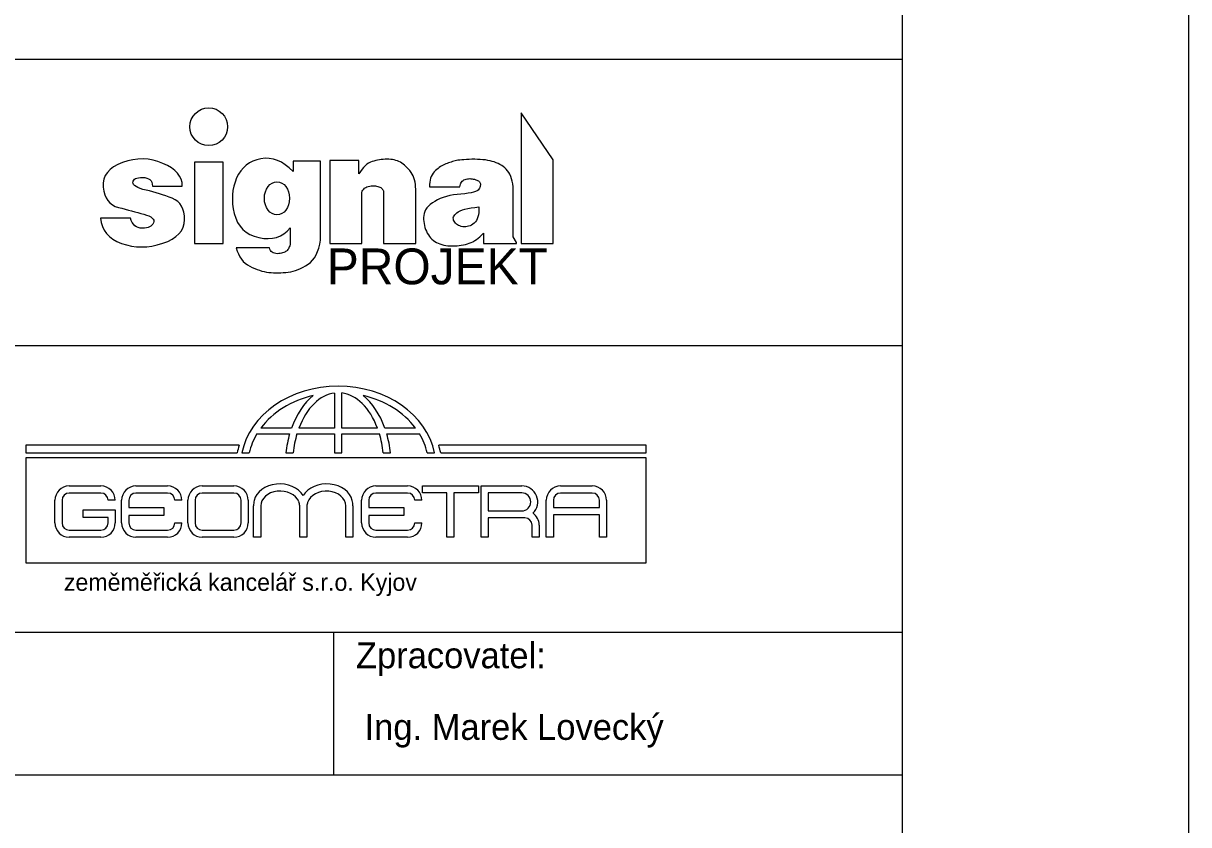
# Model space of a CAD drawing. Extents: x 3181 to 4881, y -3016 to -2572.
# Drawn here: x 4054.2 to 4135.6, y -2917.2 to -2861.3 of the extents above; entities that cross this region are included whole.
import ezdxf

# ---------------------------------------------------------------- set-up
doc = ezdxf.new("R2010")
doc.units = 0
for name, color, linetype in [('Default', 7, 'Continuous'), ('Vrstva 1', 7, 'Continuous'), ('Vrstva 11', 7, 'Continuous'), ('Vrstva 17', 7, 'Continuous'), ('Vrstva 6', 7, 'Continuous')]:
    doc.layers.add(name, color=color, linetype=linetype)

msp = doc.modelspace()

# ---------------------------------------------------------------- linework, layer by layer
at = {"layer": 'Default'}
msp.add_lwpolyline([(3925.563, -3015.765), (4135.563, -3015.765), (4135.563, -2718.765), (3925.563, -2718.765)], close=True, dxfattribs=at)
at = {"layer": 'Vrstva 1'}
msp.add_lwpolyline([(3945.563, -2738.765), (4115.563, -2738.765), (4115.563, -2998.765), (3945.563, -2998.765)], close=True, dxfattribs=at)
at = {"layer": 'Vrstva 11'}
for points in [[(4091.228, -2876.644), (4091.228, -2870.804), (4088.988, -2867.524), (4088.988, -2876.644), (4091.228, -2876.644)], [(4062.499, -2876.879), (4062.861, -2876.862), (4063.228, -2876.814), (4063.599, -2876.735), (4063.975, -2876.625), (4064.329, -2876.489), (4064.637, -2876.333), (4064.898, -2876.157), (4065.112, -2875.961), (4065.28, -2875.745), (4065.4, -2875.509), (4065.474, -2875.253), (4065.5, -2874.977), (4065.49, -2874.704), (4065.451, -2874.455), (4065.385, -2874.231), (4065.291, -2874.031), (4065.17, -2873.856), (4065.021, -2873.706), (4064.844, -2873.581), (4064.639, -2873.48), (4064.42, -2873.394), (4064.198, -2873.312), (4063.973, -2873.235), (4063.747, -2873.162), (4063.518, -2873.094), (4063.287, -2873.029), (4063.054, -2872.97), (4062.818, -2872.914), (4062.596, -2872.859), (4062.405, -2872.8), (4062.244, -2872.737), (4062.114, -2872.67), (4062.014, -2872.599), (4061.945, -2872.524), (4061.906, -2872.445), (4061.897, -2872.362), (4061.914, -2872.282), (4061.95, -2872.213), (4062.006, -2872.155), (4062.082, -2872.108), (4062.178, -2872.072), (4062.294, -2872.046), (4062.429, -2872.032), (4062.585, -2872.028), (4062.74, -2872.039), (4062.875, -2872.068), (4062.99, -2872.115), (4063.085, -2872.181), (4063.16, -2872.265), (4063.214, -2872.367), (4063.249, -2872.487), (4063.263, -2872.626), (4065.342, -2872.626), (4065.323, -2872.384), (4065.261, -2872.155), (4065.156, -2871.937), (4065.008, -2871.733), (4064.817, -2871.542), (4064.583, -2871.363), (4064.307, -2871.197), (4063.987, -2871.043), (4063.645, -2870.914), (4063.3, -2870.819), (4062.952, -2870.76), (4062.602, -2870.735), (4062.249, -2870.745), (4061.894, -2870.79), (4061.535, -2870.869), (4061.174, -2870.984), (4060.836, -2871.126), (4060.547, -2871.289), (4060.306, -2871.472), (4060.114, -2871.676), (4059.971, -2871.901), (4059.876, -2872.145), (4059.83, -2872.411), (4059.832, -2872.697), (4059.872, -2872.978), (4059.938, -2873.23), (4060.03, -2873.453), (4060.148, -2873.645), (4060.293, -2873.809), (4060.464, -2873.943), (4060.661, -2874.047), (4060.885, -2874.122), (4061.12, -2874.182), (4061.351, -2874.241), (4061.578, -2874.3), (4061.802, -2874.359), (4062.023, -2874.418), (4062.239, -2874.476), (4062.452, -2874.534), (4062.662, -2874.592), (4062.854, -2874.652), (4063.016, -2874.716), (4063.146, -2874.785), (4063.246, -2874.859), (4063.314, -2874.937), (4063.352, -2875.019), (4063.359, -2875.106), (4063.335, -2875.197), (4063.289, -2875.285), (4063.228, -2875.362), (4063.152, -2875.426), (4063.062, -2875.479), (4062.958, -2875.521), (4062.84, -2875.551), (4062.707, -2875.569), (4062.559, -2875.576), (4062.411, -2875.566), (4062.275, -2875.532), (4062.152, -2875.477), (4062.04, -2875.398), (4061.942, -2875.297), (4061.855, -2875.173), (4061.781, -2875.027), (4061.72, -2874.858), (4059.639, -2874.858), (4059.683, -2875.165), (4059.767, -2875.447), (4059.89, -2875.705), (4060.052, -2875.939), (4060.254, -2876.148), (4060.496, -2876.333), (4060.778, -2876.494), (4061.099, -2876.631), (4061.442, -2876.74), (4061.79, -2876.817), (4062.142, -2876.864), (4062.499, -2876.879)], [(4068.188, -2876.644), (4068.188, -2870.964), (4066.188, -2870.964), (4066.188, -2876.644), (4068.188, -2876.644)], [(4072.047, -2878.686), (4072.216, -2878.682), (4072.386, -2878.674), (4072.558, -2878.66), (4072.731, -2878.642), (4072.905, -2878.615), (4073.079, -2878.576), (4073.253, -2878.525), (4073.426, -2878.462), (4073.6, -2878.386), (4073.772, -2878.298), (4073.945, -2878.199), (4074.117, -2878.087), (4074.282, -2877.957), (4074.43, -2877.804), (4074.563, -2877.629), (4074.679, -2877.43), (4074.78, -2877.208), (4074.865, -2876.963), (4074.934, -2876.695), (4074.988, -2876.404), (4074.988, -2870.884), (4073.068, -2870.884), (4073.068, -2871.604), (4072.802, -2871.349), (4072.531, -2871.136), (4072.257, -2870.964), (4071.978, -2870.833), (4071.695, -2870.743), (4071.407, -2870.694), (4071.116, -2870.687), (4070.82, -2870.72), (4070.533, -2870.788), (4070.267, -2870.885), (4070.024, -2871.011), (4069.802, -2871.164), (4069.602, -2871.347), (4069.423, -2871.558), (4069.267, -2871.797), (4069.132, -2872.065), (4069.022, -2872.351), (4068.937, -2872.644), (4068.878, -2872.944), (4068.845, -2873.251), (4068.838, -2873.566), (4068.857, -2873.888), (4068.901, -2874.216), (4068.972, -2874.553), (4069.072, -2874.876), (4069.205, -2875.167), (4069.37, -2875.425), (4069.568, -2875.65), (4069.799, -2875.843), (4070.062, -2876.003), (4070.358, -2876.13), (4070.687, -2876.225), (4071.023, -2876.283), (4071.342, -2876.3), (4071.643, -2876.277), (4071.926, -2876.213), (4072.191, -2876.108), (4072.438, -2875.963), (4072.668, -2875.776), (4072.88, -2875.55), (4072.88, -2876.626), (4072.861, -2876.714), (4072.838, -2876.796), (4072.81, -2876.871), (4072.778, -2876.942), (4072.742, -2877.006), (4072.701, -2877.065), (4072.655, -2877.118), (4072.605, -2877.165), (4072.55, -2877.207), (4072.487, -2877.243), (4072.417, -2877.274), (4072.34, -2877.3), (4072.256, -2877.32), (4072.165, -2877.335), (4072.067, -2877.344), (4071.962, -2877.348), (4071.858, -2877.343), (4071.765, -2877.324), (4071.682, -2877.292), (4071.609, -2877.247), (4071.546, -2877.189), (4071.493, -2877.117), (4071.451, -2877.032), (4071.418, -2876.934), (4069.111, -2876.934), (4069.18, -2877.162), (4069.264, -2877.371), (4069.361, -2877.561), (4069.472, -2877.732), (4069.596, -2877.885), (4069.735, -2878.019), (4069.887, -2878.134), (4070.053, -2878.23), (4070.225, -2878.313), (4070.396, -2878.387), (4070.565, -2878.453), (4070.733, -2878.51), (4070.899, -2878.558), (4071.064, -2878.598), (4071.227, -2878.629), (4071.389, -2878.652), (4071.551, -2878.668), (4071.715, -2878.679), (4071.88, -2878.685), (4072.047, -2878.686)], [(4081.628, -2876.644), (4081.628, -2872.844), (4081.624, -2872.674), (4081.61, -2872.511), (4081.586, -2872.354), (4081.55, -2872.204), (4081.504, -2872.06), (4081.447, -2871.924), (4081.379, -2871.793), (4081.301, -2871.67), (4081.216, -2871.553), (4081.129, -2871.445), (4081.04, -2871.345), (4080.949, -2871.254), (4080.856, -2871.17), (4080.761, -2871.095), (4080.664, -2871.028), (4080.565, -2870.969), (4080.462, -2870.918), (4080.356, -2870.873), (4080.245, -2870.836), (4080.13, -2870.806), (4080.011, -2870.782), (4079.887, -2870.765), (4079.759, -2870.756), (4079.627, -2870.753), (4079.493, -2870.756), (4079.361, -2870.764), (4079.229, -2870.777), (4079.099, -2870.795), (4078.97, -2870.818), (4078.842, -2870.846), (4078.716, -2870.879), (4078.59, -2870.917), (4078.467, -2870.965), (4078.345, -2871.03), (4078.226, -2871.111), (4078.11, -2871.209), (4077.996, -2871.323), (4077.884, -2871.453), (4077.775, -2871.6), (4077.668, -2871.764), (4077.668, -2870.844), (4075.628, -2870.844), (4075.628, -2876.644), (4077.868, -2876.644), (4077.868, -2873.084), (4077.902, -2872.993), (4077.946, -2872.912), (4078.001, -2872.841), (4078.065, -2872.78), (4078.139, -2872.729), (4078.223, -2872.688), (4078.317, -2872.657), (4078.421, -2872.636), (4078.527, -2872.623), (4078.628, -2872.616), (4078.723, -2872.615), (4078.814, -2872.62), (4078.899, -2872.632), (4078.978, -2872.649), (4079.053, -2872.673), (4079.122, -2872.703), (4079.184, -2872.737), (4079.238, -2872.776), (4079.284, -2872.818), (4079.321, -2872.864), (4079.35, -2872.913), (4079.371, -2872.966), (4079.383, -2873.023), (4079.388, -2873.084), (4079.388, -2876.644), (4081.628, -2876.644)], [(4084.19, -2876.808), (4084.352, -2876.805), (4084.51, -2876.796), (4084.663, -2876.782), (4084.812, -2876.762), (4084.956, -2876.736), (4085.097, -2876.705), (4085.233, -2876.667), (4085.364, -2876.624), (4085.493, -2876.573), (4085.62, -2876.511), (4085.746, -2876.44), (4085.869, -2876.357), (4085.991, -2876.264), (4086.112, -2876.161), (4086.23, -2876.048), (4086.348, -2875.924), (4086.348, -2876.644), (4088.668, -2876.644), (4088.668, -2876.564), (4088.428, -2876.164), (4088.428, -2872.684), (4088.401, -2872.479), (4088.365, -2872.289), (4088.32, -2872.113), (4088.265, -2871.952), (4088.201, -2871.805), (4088.127, -2871.673), (4088.043, -2871.555), (4087.95, -2871.452), (4087.849, -2871.359), (4087.742, -2871.273), (4087.628, -2871.195), (4087.508, -2871.123), (4087.382, -2871.058), (4087.25, -2871), (4087.111, -2870.948), (4086.966, -2870.904), (4086.814, -2870.866), (4086.655, -2870.834), (4086.489, -2870.808), (4086.315, -2870.787), (4086.135, -2870.772), (4085.947, -2870.763), (4085.751, -2870.759), (4085.549, -2870.761), (4085.35, -2870.767), (4085.166, -2870.775), (4084.997, -2870.786), (4084.843, -2870.799), (4084.703, -2870.814), (4084.578, -2870.831), (4084.467, -2870.85), (4084.372, -2870.872), (4084.283, -2870.896), (4084.194, -2870.921), (4084.104, -2870.949), (4084.013, -2870.978), (4083.921, -2871.01), (4083.829, -2871.043), (4083.737, -2871.079), (4083.643, -2871.116), (4083.55, -2871.158), (4083.458, -2871.206), (4083.366, -2871.262), (4083.276, -2871.324), (4083.187, -2871.393), (4083.099, -2871.469), (4083.012, -2871.551), (4082.926, -2871.641), (4082.845, -2871.738), (4082.776, -2871.845), (4082.718, -2871.962), (4082.67, -2872.087), (4082.633, -2872.222), (4082.607, -2872.367), (4082.592, -2872.521), (4082.588, -2872.684), (4084.708, -2872.684), (4084.723, -2872.587), (4084.747, -2872.5), (4084.78, -2872.422), (4084.821, -2872.353), (4084.872, -2872.294), (4084.93, -2872.243), (4084.998, -2872.202), (4085.073, -2872.169), (4085.154, -2872.145), (4085.235, -2872.127), (4085.317, -2872.116), (4085.399, -2872.111), (4085.481, -2872.113), (4085.565, -2872.121), (4085.648, -2872.136), (4085.732, -2872.157), (4085.813, -2872.183), (4085.884, -2872.211), (4085.947, -2872.24), (4086, -2872.272), (4086.045, -2872.307), (4086.082, -2872.343), (4086.109, -2872.381), (4086.128, -2872.422), (4086.14, -2872.465), (4086.145, -2872.511), (4086.144, -2872.559), (4086.136, -2872.611), (4086.122, -2872.665), (4086.103, -2872.722), (4086.076, -2872.782), (4086.044, -2872.844), (4085.993, -2872.905), (4085.912, -2872.961), (4085.801, -2873.012), (4085.659, -2873.057), (4085.487, -2873.097), (4085.285, -2873.132), (4085.052, -2873.162), (4084.789, -2873.186), (4084.517, -2873.212), (4084.258, -2873.25), (4084.01, -2873.298), (4083.775, -2873.356), (4083.553, -2873.425), (4083.342, -2873.505), (4083.144, -2873.595), (4082.958, -2873.695), (4082.789, -2873.804), (4082.641, -2873.916), (4082.513, -2874.033), (4082.407, -2874.155), (4082.321, -2874.281), (4082.256, -2874.412), (4082.212, -2874.547), (4082.189, -2874.687), (4082.181, -2874.828), (4082.182, -2874.968), (4082.192, -2875.107), (4082.211, -2875.245), (4082.239, -2875.382), (4082.276, -2875.517), (4082.322, -2875.652), (4082.377, -2875.785), (4082.44, -2875.913), (4082.51, -2876.032), (4082.587, -2876.143), (4082.671, -2876.244), (4082.761, -2876.337), (4082.859, -2876.421), (4082.964, -2876.495), (4083.075, -2876.562), (4083.193, -2876.619), (4083.317, -2876.669), (4083.447, -2876.712), (4083.584, -2876.746), (4083.726, -2876.773), (4083.875, -2876.792), (4084.03, -2876.804), (4084.19, -2876.808)], [(4084.906, -2875.463), (4084.803, -2875.443), (4084.708, -2875.415), (4084.622, -2875.379), (4084.543, -2875.335), (4084.472, -2875.284), (4084.409, -2875.225), (4084.354, -2875.158), (4084.307, -2875.083), (4084.273, -2875.006), (4084.255, -2874.929), (4084.254, -2874.853), (4084.27, -2874.778), (4084.302, -2874.703), (4084.351, -2874.63), (4084.417, -2874.558), (4084.5, -2874.486), (4084.603, -2874.418), (4084.732, -2874.355), (4084.886, -2874.297), (4085.065, -2874.245), (4085.269, -2874.198), (4085.498, -2874.156), (4085.753, -2874.119), (4086.032, -2874.088), (4086.037, -2874.287), (4086.028, -2874.469), (4086.006, -2874.635), (4085.972, -2874.784), (4085.924, -2874.918), (4085.864, -2875.035), (4085.79, -2875.137), (4085.704, -2875.222), (4085.611, -2875.293), (4085.515, -2875.353), (4085.418, -2875.4), (4085.319, -2875.436), (4085.219, -2875.461), (4085.116, -2875.473), (4085.012, -2875.474), (4084.906, -2875.463)]]:
    msp.add_lwpolyline(points, dxfattribs=at)
msp.add_circle((4067.188, -2868.484), 1.32, dxfattribs=at)
msp.add_ellipse((4071.948, -2873.484), major_axis=(0, 1.16), ratio=0.758621, dxfattribs=at)
at = {"layer": 'Vrstva 17'}
for p, q in [((4075.958, -2887.077), (4075.958, -2889.523)), ((4076.465, -2889.523), (4076.465, -2887.075)), ((4072.965, -2889.523), (4070.82, -2889.523)), ((4075.958, -2889.523), (4073.482, -2889.523)), ((4078.96, -2889.523), (4076.465, -2889.523)), ((4081.622, -2889.523), (4079.477, -2889.523)), ((4070.545, -2889.935), (4072.832, -2889.935)), ((4073.342, -2889.935), (4075.958, -2889.935)), ((4075.958, -2889.935), (4075.958, -2891.255)), ((4076.465, -2891.255), (4076.465, -2889.935)), ((4076.465, -2889.935), (4079.099, -2889.935)), ((4079.609, -2889.935), (4081.897, -2889.935)), ((4069.314, -2890.724), (4054.433, -2890.724)), ((4054.433, -2890.724), (4054.433, -2891.255)), ((4054.433, -2891.255), (4069.176, -2891.255)), ((4069.502, -2891.255), (4070.019, -2891.255)), ((4072.575, -2891.255), (4073.075, -2891.255)), ((4075.958, -2891.255), (4076.465, -2891.255)), ((4079.366, -2891.255), (4079.866, -2891.255)), ((4082.423, -2891.255), (4082.94, -2891.255)), ((4097.712, -2890.724), (4083.233, -2890.724)), ((4083.371, -2891.255), (4097.712, -2891.255)), ((4097.712, -2891.255), (4097.712, -2890.724)), ((4097.71, -2891.599), (4054.427, -2891.599)), ((4054.427, -2891.599), (4054.427, -2898.937)), ((4097.71, -2898.937), (4097.71, -2891.599)), ((4057.452, -2893.565), (4059.663, -2893.565)), ((4062.108, -2893.565), (4064.319, -2893.565)), ((4066.732, -2893.565), (4068.943, -2893.565)), ((4078.851, -2893.565), (4081.061, -2893.565)), ((4086.188, -2893.565), (4089.032, -2893.565)), ((4091.736, -2893.565), (4093.947, -2893.565)), ((4056.454, -2896.149), (4056.454, -2894.563)), ((4056.953, -2894.563), (4056.953, -2896.149)), ((4059.663, -2894.064), (4057.452, -2894.064)), ((4060.66, -2894.563), (4060.162, -2894.563)), ((4061.11, -2896.149), (4061.11, -2894.563)), ((4061.609, -2894.563), (4061.609, -2895.074)), ((4064.319, -2894.064), (4062.108, -2894.064)), ((4065.317, -2894.563), (4064.818, -2894.563)), ((4065.734, -2896.149), (4065.734, -2894.563)), ((4066.233, -2894.563), (4066.233, -2896.149)), ((4068.943, -2894.064), (4066.732, -2894.064)), ((4069.442, -2896.149), (4069.442, -2894.563)), ((4069.941, -2894.563), (4069.941, -2896.149)), ((4077.853, -2896.149), (4077.853, -2894.563)), ((4078.352, -2894.563), (4078.352, -2895.074)), ((4081.061, -2894.064), (4078.851, -2894.064)), ((4082.059, -2894.563), (4081.56, -2894.563)), ((4083.794, -2897.147), (4083.794, -2894.052)), ((4084.297, -2894.052), (4084.297, -2897.147)), ((4089.032, -2894.054), (4086.692, -2894.054)), ((4086.692, -2894.054), (4086.692, -2895.304)), ((4090.738, -2897.147), (4090.738, -2894.563)), ((4091.237, -2894.563), (4091.237, -2895.072)), ((4093.947, -2894.064), (4091.736, -2894.064)), ((4094.446, -2895.072), (4094.446, -2894.563)), ((4094.945, -2894.563), (4094.945, -2897.147)), ((4058.427, -2895.771), (4058.427, -2895.227)), ((4058.427, -2895.227), (4060.66, -2895.227)), ((4060.66, -2895.227), (4060.66, -2896.149)), ((4061.609, -2895.074), (4064.052, -2895.074)), ((4064.052, -2895.074), (4064.052, -2895.618)), ((4070.313, -2897.147), (4070.313, -2894.962)), ((4070.814, -2894.962), (4070.814, -2897.147)), ((4073.533, -2897.147), (4073.533, -2894.962)), ((4074.033, -2894.962), (4074.033, -2897.147)), ((4076.752, -2897.147), (4076.752, -2894.962)), ((4077.253, -2894.962), (4077.253, -2897.147)), ((4078.352, -2895.074), (4080.795, -2895.074)), ((4080.795, -2895.074), (4080.795, -2895.618)), ((4086.692, -2895.304), (4089.032, -2895.304)), ((4091.237, -2895.072), (4094.446, -2895.072)), ((4060.162, -2895.771), (4058.427, -2895.771)), ((4060.162, -2896.149), (4060.162, -2895.771)), ((4064.052, -2895.618), (4061.609, -2895.618)), ((4061.609, -2895.618), (4061.609, -2896.149)), ((4064.818, -2896.149), (4065.317, -2896.149)), ((4080.795, -2895.618), (4078.352, -2895.618)), ((4078.352, -2895.618), (4078.352, -2896.149)), ((4081.56, -2896.149), (4082.059, -2896.149)), ((4089.032, -2895.793), (4086.692, -2895.793)), ((4089.247, -2895.797), (4089.032, -2895.793)), ((4089.746, -2897.147), (4089.746, -2896.296)), ((4090.244, -2896.296), (4090.244, -2897.147)), ((4094.446, -2895.575), (4091.237, -2895.575)), ((4091.237, -2895.575), (4091.237, -2897.147)), ((4094.446, -2897.147), (4094.446, -2895.575)), ((4057.452, -2896.648), (4059.663, -2896.648)), ((4059.663, -2897.147), (4057.452, -2897.147)), ((4062.108, -2896.648), (4064.319, -2896.648)), ((4064.319, -2897.147), (4062.108, -2897.147)), ((4066.732, -2896.648), (4068.943, -2896.648)), ((4068.943, -2897.147), (4066.732, -2897.147)), ((4070.814, -2897.147), (4070.313, -2897.147)), ((4074.033, -2897.147), (4073.533, -2897.147)), ((4077.253, -2897.147), (4076.752, -2897.147)), ((4078.851, -2896.648), (4081.061, -2896.648)), ((4081.061, -2897.147), (4078.851, -2897.147)), ((4084.297, -2897.147), (4083.794, -2897.147)), ((4090.244, -2897.147), (4089.746, -2897.147)), ((4091.237, -2897.147), (4090.738, -2897.147)), ((4094.945, -2897.147), (4094.446, -2897.147)), ((4054.427, -2898.937), (4097.71, -2898.937))]:
    msp.add_line(p, q, dxfattribs=at)
for points in [[(4083.794, -2894.052), (4082.096, -2894.052), (4082.096, -2893.565), (4086.009, -2893.565)], [(4086.009, -2893.565), (4086.009, -2894.052), (4084.297, -2894.052)], [(4086.692, -2895.793), (4086.692, -2897.147), (4086.188, -2897.147), (4086.188, -2893.565)]]:
    msp.add_lwpolyline(points, dxfattribs=at)
for centre, radius, start, end in [((4057.452, -2894.563), 0.998, 90, 180), ((4059.663, -2894.563), 0.998, 360, 90), ((4062.108, -2894.563), 0.998, 90, 180), ((4064.319, -2894.563), 0.998, 360, 90), ((4066.732, -2894.563), 0.998, 90, 180), ((4068.943, -2894.563), 0.998, 360, 90), ((4078.851, -2894.563), 0.998, 90, 180), ((4081.061, -2894.563), 0.998, 360, 90), ((4089.032, -2894.679), 1.114, 314.45734, 90), ((4091.736, -2894.563), 0.998, 90, 180), ((4093.947, -2894.563), 0.998, 360, 90), ((4057.452, -2894.563), 0.499, 90, 180), ((4059.663, -2894.563), 0.499, 0, 90), ((4062.108, -2894.563), 0.499, 90, 180), ((4064.319, -2894.563), 0.499, 0, 90), ((4066.732, -2894.563), 0.499, 90, 180), ((4068.943, -2894.563), 0.499, 0, 90), ((4072.25, -2895.012), 1.938, 166.96576, 178.52091), ((4072.579, -2895.027), 0.957, 3.86486, 22.41569), ((4075.266, -2895.084), 1.238, 162.61388, 174.3506), ((4075.315, -2895.012), 1.938, 1.47909, 13.03424), ((4078.851, -2894.563), 0.499, 90, 180), ((4081.061, -2894.563), 0.499, 0, 90), ((4089.032, -2894.679), 0.625, 270, 90), ((4091.736, -2894.563), 0.499, 90, 180), ((4093.947, -2894.563), 0.499, 0, 90), ((4089.247, -2896.296), 0.998, 360, 55.44734), ((4057.452, -2896.149), 0.998, 180, 270), ((4057.452, -2896.149), 0.499, 180, 270), ((4059.663, -2896.149), 0.998, 270, 0), ((4059.663, -2896.149), 0.499, 270, 0), ((4062.108, -2896.149), 0.998, 180, 270), ((4062.108, -2896.149), 0.499, 180, 270), ((4064.319, -2896.149), 0.998, 270, 0), ((4064.319, -2896.149), 0.499, 270, 0), ((4066.732, -2896.149), 0.998, 180, 270), ((4066.732, -2896.149), 0.499, 180, 270), ((4068.943, -2896.149), 0.998, 270, 0), ((4068.943, -2896.149), 0.499, 270, 0), ((4078.851, -2896.149), 0.998, 180, 270), ((4078.851, -2896.149), 0.499, 180, 270), ((4081.061, -2896.149), 0.998, 270, 0), ((4081.061, -2896.149), 0.499, 270, 0), ((4089.247, -2896.296), 0.499, 0, 90)]:
    msp.add_arc(centre, radius, start, end, dxfattribs=at)
for centre, major_axis, ratio, start_param, end_param in [((4076.221, -2892.127), (-6.804, 0), 0.811768, 3.300239, 6.124539), ((4076.221, -2892.127), (-6.296, 0), 0.804826, 4.992897, 5.743383), ((4076.221, -2892.127), (0, 5.524), 0.668443, 0.491666, 1.079789), ((4076.221, -2892.127), (0, 5.067), 0.630136, 0.08224, 1.030995), ((4076.221, -2892.127), (0, 5.067), 0.630136, 5.252191, 6.206521), ((4076.221, -2892.127), (0, 5.524), 0.668443, 5.203397, 5.79152), ((4076.221, -2892.127), (-6.296, 0), 0.804826, 3.681394, 4.431881), ((4076.221, -2892.127), (-6.296, 0), 0.804826, 5.835664, 6.110118), ((4076.221, -2892.127), (0, 5.524), 0.668443, 1.16256, 1.41215), ((4076.221, -2892.127), (0, 5.067), 0.630136, 1.123275, 1.397729), ((4076.221, -2892.127), (0, 5.067), 0.630136, 4.885456, 5.159911), ((4076.221, -2892.127), (0, 5.524), 0.668443, 4.871035, 5.120625), ((4076.221, -2892.127), (-6.296, 0), 0.804826, 3.31466, 3.589114), ((4075.895, -2892.127), (-6.804, 0), 0.811768, 6.026233, 6.124539), ((4076.653, -2892.127), (-6.804, 0), 0.811768, 3.300239, 3.398545), ((4072.142, -2894.807), (1.805, 0), 0.766187, 0.429647, 2.97338), ((4072.167, -2894.962), (1.354, 0), 0.766187, 0.29376, 3.141593), ((4075.424, -2894.807), (-1.805, 0), 0.766187, 3.309805, 5.853538), ((4075.398, -2894.962), (-1.354, 0), 0.766187, 3.141593, 6.041607)]:
    msp.add_ellipse(centre, major_axis=major_axis, ratio=ratio, start_param=start_param, end_param=end_param, dxfattribs=at)
at = {"layer": 'Vrstva 6'}
for p, q in [((3945.563, -2883.765), (4115.563, -2883.765)), ((3945.563, -2903.765), (4115.563, -2903.765)), ((4075.913, -2913.765), (4075.913, -2903.765))]:
    msp.add_line(p, q, dxfattribs=at)
msp.add_lwpolyline([(3945.563, -2863.765), (4115.563, -2863.765), (4115.563, -2913.765), (3945.563, -2913.765)], close=True, dxfattribs=at)

# ---------------------------------------------------------------- texts
at = {"layer": 'Vrstva 11'}
msp.add_text('PROJEKT', height=2.5, dxfattribs=at).set_placement((4075.428, -2879.487))
at = {"layer": 'Vrstva 17'}
msp.add_text('zeměměřická kancelář s.r.o. Kyjov', height=1.20984, dxfattribs=at).set_placement((4057.079, -2900.886))
at = {"layer": 'Vrstva 6'}
for s, p in [('Zpracovatel:', (4077.459, -2906.291)), ('Ing. Marek Lovecký', (4078.06, -2911.291))]:
    msp.add_text(s, height=1.8, dxfattribs=at).set_placement(p)

doc.saveas('drawing.dxf')
